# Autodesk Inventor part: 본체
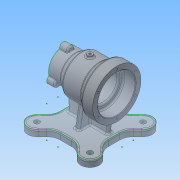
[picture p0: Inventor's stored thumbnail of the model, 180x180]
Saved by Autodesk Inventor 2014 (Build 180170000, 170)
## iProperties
Created: 2017-03
Part Number: 본체
Material: 일반
Document SubType Name: Modeling
Designer: NET
Density: 1 g/cm^3
Appearance: 기본값
Author: NET
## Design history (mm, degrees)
sketch "스케치1"
  geometry: L1 (-45, 45)-(45, 45); L2 (45, 45)-(45, -45); L3 (45, -45)-(-45, -45); L4 (-45, -45)-(-45, 45); L5 (-12.021, 12.021)-(-49.497, 49.497); L6 (0, 0)-(-49.497, -49.497); L7 (0, 0)-(-38.765, 0); L8 (-24.042, 0)-(-61.518, -37.477); L9 (0, -24.042)-(-37.477, -61.518); L10 (-24.042, 0)-(-73.539, 49.497); L11 (0, 24.042)-(-49.497, 73.539); L12 (12.021, -12.021)-(49.497, -49.497); L13 (0, 0)-(49.497, 49.497); L14 (24.042, 0)-(73.539, -49.497); L15 (0, -24.042)-(49.497, -73.539); L16 (0, 24.042)-(37.477, 61.518); L17 (24.042, 0)-(61.518, 37.477); C1 r 17 at (-49.497, 49.497); C2 r 17 at (-49.497, -49.497); C3 r 17 at (49.497, 49.497); C4 r 17 at (49.497, -49.497); A1 r 70 centre (0, 0) between (-60.036, -35.995) and (-35.995, -60.036); A2 r 70 centre (0, 0) between (35.995, -60.036) and (60.036, -35.995); A3 r 70 centre (0, 0) between (60.036, 35.995) and (35.995, 60.036); A4 r 70 centre (0, 0) between (-35.995, 60.036) and (-60.036, 35.995); A5 r 25 centre (-70, 10.603) between (-45, 10.603) and (-52.322, 28.281); A6 r 25 centre (-70, -10.603) between (-52.322, -28.281) and (-45, -10.603); A7 r 25 centre (-10.603, -70) between (-10.603, -45) and (-28.281, -52.322); A8 r 25 centre (10.603, -70) between (28.281, -52.322) and (10.603, -45); A9 r 25 centre (70, 10.603) between (52.322, 28.281) and (45, 10.603); A10 r 25 centre (70, -10.603) between (45, -10.603) and (52.322, -28.281); A11 r 25 centre (-10.603, 70) between (-28.281, 52.322) and (-10.603, 45); A12 r 25 centre (10.603, 70) between (10.603, 45) and (28.281, 52.322); 3 further points
  constraints: 34 end point, 29 point on circle, 25 point on line, 16 centre point, 16 tangent, 10 parallel, 4 coincident, 2 midpoint, 2 perpendicular, 1 horizontal, 1 horizontal alignment, 1 vertical alignment
  dimensions: "d0" = 90 distance of L1.start L1.end; "d1" = 90 distance of L1.end L2.end; "d3" = 45 deg angle of L7 L5; "d4" = 45 deg angle of L6 L7; "d5" = 34 diameter of C1; "d6" = 34 diameter of C2; "d7" = 17 distance between parallel lines of L11 L5; "d8" = 17 distance between parallel lines of L5 L10; "d9" = 17 distance between parallel lines of L8 L6; "d10" = 17 distance between parallel lines of L9 L6; "d11" = 49.49747 horizontal distance of point (0, 0) C2.centre; "d12" = 45 deg angle of L7 L13; "d13" = 45 deg angle of L7 L12; "d14" = 34 diameter of C3; "d15" = 34 diameter of C4; "d16" = 17 distance between parallel lines of L16 L13; "d17" = 17 distance between parallel lines of L17 L13; "d18" = 17 distance between parallel lines of L14 L12; "d19" = 17 distance between parallel lines of L15 L12; "d20" = 49.49747 horizontal distance of point (0, 0) L5.end; "d21" = 70 distance from line of L12 L13.end; "d22" = 49.49747 horizontal distance of point (0, 0) L6.end; "d23" = 49.49747 horizontal distance of point (0, 0) C4.centre; "d26" = 50 diameter of A5; "d27" = 50 diameter of A6; "d28" = 50 diameter of A7; "d29" = 50 diameter of A8; "d30" = 50 diameter of A9; "d31" = 50 diameter of A10; "d32" = 50 diameter of A11; "d33" = 50 diameter of A12; "d34" = 25 radius of A5 (derived); "d35" = 70 distance of L9.start L15.end; "d36" = 70 distance of L14.start L14.end; "d37" = 70 distance of L12.start L17.end; "d38" = 70 distance of L5.start L16.end; "d39" = 70 distance of L11.start L11.end; "d40" = 70 distance of L8.start L10.end; "d41" = 70 distance of L5.start L8.end; "d42" = 70 distance of L12.start L9.end; "d43" = 70 distance of L6.start L13.end (derived); "d44" = 70 radius of A4 (derived); "d45" = 70 radius of A1 (derived); "d46" = 90 distance of L3.end L1.start (derived); "d47" = 12.02082 horizontal distance of L12.start point (0, 0); "d48" = 12.02082 horizontal distance of L12.start point (0, 0); "d49" = 12.02082 horizontal distance of L5.start point (0, 0); "d50" = 12.02082 horizontal distance of point (0, 0) L5.start (derived); "d51" = 24.04163 distance of point (0, 0) L8.start (derived); "d52" = 38.76502 distance of L6.start L7.end
extrude "돌출1" new body sketch "스케치1" distance "d53" = 12; taper "d54" = 0 deg
sketch "스케치2"
  geometry: L1 (-50, 82)-(50, 82); L2 (10.603, 0)-(-10.603, 0) reference; L3 (-50, 82)-(-50, 127); L4 (-50, 127)-(-30, 127); L5 (-30, 127)-(-19, 118); L6 (-19, 118)-(15, 118); L7 (15, 118)-(27, 109.5); L8 (27, 109.5)-(50, 109.5); L9 (50, 109.5)-(50, 82); L10 (-50, 117)-(-27, 117); L11 (-27, 117)-(-27, 108); L12 (-27, 108)-(20, 108); L13 (20, 108)-(20, 99.5); L14 (20, 99.5)-(50, 99.5); 3 further points
  constraints: 26 end point, 5 parallel, 5 perpendicular, 2 midpoint, 2 point on line, 1 horizontal, 1 vertical alignment
  dimensions: "d55" = 100 distance of L1.start L1.end; "d56" = 82 vertical distance of point (0, 0) L1.start; "d57" = 90 diameter of L4 L1; "d58" = 72 diameter of L6 L1; "d59" = 55 diameter of L8 L1; "d60" = 20 distance of L3.end L4.end; "d61" = 31 horizontal distance of L5.end L3.end; "d62" = 65 horizontal distance of L6.end L3.end; "d63" = 23 distance of L7.end L8.end; "d64" = 23 distance of L10.start L10.end; "d65" = 47 distance of L11.end L12.end; "d67" = 70 diameter of L10 L1; "d68" = 52 diameter of L12 L1; "d69" = 35 diameter of L14 L1
revolve "회전1" stored, may be unused: angle "d70" = 90 deg
sketch "스케치3"
  geometry: L1 (10.603, 0)-(-10.603, 0) reference; L2 (10.603, 12)-(-10.603, 12) reference; L3 (0, 12)-(-37, 12); L4 (-37, 12)-(-37, 72); L5 (-37, 72)-(37, 72); L6 (37, 72)-(37, 12); L7 (37, 12)-(0, 12); 1 further point
  constraints: 10 end point, 2 perpendicular, 2 point on line, 1 collinear, 1 midpoint, 1 parallel
  dimensions: "d71" = 37 distance of L3.end L3.start; "d72" = 37 distance of L6.end L3.start; "d73" = 60 distance of L3.end L4.end
extrude "돌출2" join sketch "스케치3" stored distance "d74" = 8; taper "d75" = 0 deg
sketch "스케치4"
  geometry: L1 (10.603, 0)-(-10.603, 0) reference; L2 (4, 12)-(4, 54.792) reference; L3 (-4, 12)-(4, 12) reference; L4 (-4, 54.792)-(-4, 12) reference; L5 (0, 12)-(-25, 12); L6 (-25, 12)-(-15.302, 67); L7 (-15.302, 67)-(0, 67); L8 (0, 67)-(0, 12); L9 (0, 12)-(25, 12); L10 (25, 12)-(15.302, 67); L11 (15.302, 67)-(0, 67); L12 (-36.106, 12)-(-66.497, 12) reference; L13 (35.995, 12)-(28.281, 12) reference; A1 r 27.5 centre (0, 82) between (-4, 54.792) and (4, 54.792) reference; 2 further points
  constraints: 14 end point, 3 perpendicular, 2 parallel, 1 midpoint
  dimensions: "d76" = 25 distance of L5.start L5.end; "d77" = 25 distance of L5.start L9.end; "d78" = 100 deg angle of L6 L12; "d79" = 100 deg angle of L13 L10; "d80" = 55 distance of L7.end L5.start; "d81" = 15.30202 distance of L6.end L7.end (derived)
extrude "돌출3" join sketch "스케치4" stored distance "d82" = 8; taper "d83" = 0 deg
revolve "회전2" stored, may be unused: angle "d84" = 90 deg
sketch "스케치5"
  geometry: L1 (-107.4, 0)-(70.4, 0) reference; C1 r 7 at (27.5, 0); 2 further points
  constraints: 1 centre point, 1 horizontal alignment, 1 point on line, 1 other
  dimensions: "d85" = 14 diameter of C1
extrude "돌출4" join sketch "스케치5" distance "d86" = 15; taper "d87" = 0 deg
sketch "스케치6"
  geometry: C1 r 35 at (0, 0) reference; 2 further points
  constraints: 1 horizontal alignment
  dimensions: "d91" = 40 distance of C1.centre point (-40, 0)
hole "구멍1" sketch "스케치6" at (-40, 0) diameter "d92" = 3.242; stored, may be unused: countersink angle "d96" = 90 deg, drill point angle "d98" = 118 deg; dims "d93" = 9, "d94" = 4, "d95" = 2, "d97" = 11
sketch "스케치7"
  geometry: C1 r 17.5 at (-27.5, 0) reference; A1 r 27.5 centre (-27.5, 0) between (-34.792, -26.516) and (-0.891, -6.943) reference; A2 r 7 centre (0, 0) between (-0.891, -6.943) and (-0.891, 6.943) reference; A3 r 27.5 centre (-27.5, 0) between (-0.891, 6.943) and (-34.792, 26.516) reference; A4 r 7 centre (-41.25, 23.816) between (-34.792, 26.516) and (-46.817, 19.573) reference; A5 r 27.5 centre (-27.5, 0) between (-46.817, 19.573) and (-46.817, -19.573) reference; A6 r 7 centre (-41.25, -23.816) between (-46.817, -19.573) and (-34.792, -26.516) reference; 1 further point
hole "구멍2" diameter "d104" = 3.242; stored, may be unused: countersink angle "d108" = 90 deg, drill point angle "d110" = 118 deg; dims "d102" = 10, "d103" = 10, "d105" = 9, "d106" = 4, "d107" = 2, "d109" = 11
node "작업 평면1"
sketch "스케치8"
  geometry: L1 (4, 4)-(4, 18.14) reference; L2 (4, 18.14)-(-4, 18.14) reference; L3 (-4, 18.14)-(-4, 4) reference; L4 (-4, 4)-(-15, 4) reference; L5 (-15, -4)-(-15, 4) reference; L6 (-15, -4)-(-4, -4) reference; L7 (-4, -4)-(-4, -18.14) reference; L8 (-4, -18.14)-(4, -18.14) reference; L9 (4, -18.14)-(4, -4) reference; L10 (4, -4)-(19, -4) reference; L11 (19, -4)-(19, 4) reference; L12 (19, 4)-(4, 4) reference; L13 (50, 45)-(50, -45) reference; C1 r 5 at (0, 0); 1 further point
  constraints: 1 centre point, 1 coincident
  dimensions: "d115" = 10 diameter of C1; "d116" = 50 distance from line of C1.centre L13 (derived)
extrude "돌출5" join sketch "스케치8" stored distance "d117" = 15; taper "d118" = 0 deg
hole "구멍3" diameter "d121" = 4.134; stored, may be unused: countersink angle "d125" = 90 deg, drill point angle "d127" = 118 deg; dims "d119" = 10, "d120" = 10, "d122" = 9, "d123" = 4, "d124" = 2, "d126" = 32.25
chamfer "모따기1" distance "d128" = 1; stored, may be unused: second distance "d129" = 2, angle "d130" = 45 deg
chamfer "모따기2" distance "d131" = 1; stored, may be unused: second distance "d132" = 2, angle "d133" = 45 deg
fillet "모깎기1" dims "d134" = 3
fillet "모깎기2" dims "d135" = 3
fillet "모깎기3" dims "d136" = 3
fillet "모깎기4" dims "d137" = 1
fillet "모깎기5" dims "d138" = 3
fillet "모깎기6" dims "d139" = 1
fillet "모깎기7" dims "d140" = 3
fillet "모깎기8" dims "d141" = 1
sketch "스케치9"
  geometry: L1 (4, 25)-(4, 4) reference; L2 (4, 4)-(37, 4) reference; L3 (37, 4)-(37, -4) reference; L4 (37, -4)-(4, -4) reference; L5 (4, -4)-(4, -25) reference; L6 (4, -25)-(-4, -25) reference; L7 (-4, -25)-(-4, -4) reference; L8 (-4, -4)-(-37, -4) reference; L9 (-37, -4)-(-37, 4) reference; L10 (-37, 4)-(-4, 4) reference; L11 (-4, 4)-(-4, 25) reference; L12 (-4, 25)-(4, 25) reference; L13 (35.995, 60.036)-(28.281, 52.322) reference; L14 (10.603, 45)-(-10.603, 45) reference; L15 (-28.281, 52.322)-(-35.995, 60.036) reference; L16 (-60.036, 35.995)-(-52.322, 28.281) reference; L17 (-45, 10.603)-(-45, -10.603) reference; L18 (-52.322, -28.281)-(-60.036, -35.995) reference; L19 (-35.995, -60.036)-(-28.281, -52.322) reference; L20 (-10.603, -45)-(10.603, -45) reference; L21 (28.281, -52.322)-(35.995, -60.036) reference; L22 (60.036, -35.995)-(52.322, -28.281) reference; L23 (45, -10.603)-(45, 10.603) reference; L24 (52.322, 28.281)-(60.036, 35.995) reference; A1 r 70 centre (0, 0) between (36.106, 59.97) and (35.995, 60.036) reference; A2 r 25 centre (10.603, 70) between (10.603, 45) and (28.281, 52.322) reference; A3 r 25 centre (-10.603, 70) between (-28.281, 52.322) and (-10.603, 45) reference; A4 r 70 centre (0, 0) between (-35.995, 60.036) and (-36.106, 59.97) reference; A5 r 17 centre (-49.497, 49.497) between (-36.106, 59.97) and (-59.97, 36.106) reference; A6 r 70 centre (0, 0) between (-59.97, 36.106) and (-60.036, 35.995) reference; A7 r 25 centre (-70, 10.603) between (-45, 10.603) and (-52.322, 28.281) reference; A8 r 25 centre (-70, -10.603) between (-52.322, -28.281) and (-45, -10.603) reference; A9 r 70 centre (0, 0) between (-60.036, -35.995) and (-59.97, -36.106) reference; A10 r 17 centre (-49.497, -49.497) between (-59.97, -36.106) and (-36.106, -59.97) reference; A11 r 70 centre (0, 0) between (-36.106, -59.97) and (-35.995, -60.036) reference; A12 r 25 centre (-10.603, -70) between (-10.603, -45) and (-28.281, -52.322) reference; A13 r 25 centre (10.603, -70) between (28.281, -52.322) and (10.603, -45) reference; A14 r 70 centre (0, 0) between (35.995, -60.036) and (36.106, -59.97) reference; A15 r 17 centre (49.497, -49.497) between (36.106, -59.97) and (59.97, -36.106) reference; A16 r 70 centre (0, 0) between (59.97, -36.106) and (60.036, -35.995) reference; A17 r 25 centre (70, -10.603) between (45, -10.603) and (52.322, -28.281) reference; A18 r 25 centre (70, 10.603) between (52.322, 28.281) and (45, 10.603) reference; A19 r 70 centre (0, 0) between (60.036, 35.995) and (59.97, 36.106) reference; A20 r 17 centre (49.497, 49.497) between (59.97, 36.106) and (36.106, 59.97) reference
hole "구멍4" diameter "d144" = 10; stored, may be unused: countersink angle "d148" = 90 deg, drill point angle "d150" = 0 deg; dims "d142" = 10, "d143" = 10, "d145" = 9, "d146" = 4, "d147" = 2, "d149" = 32.25
hole "구멍5" diameter "d153" = 10; stored, may be unused: countersink angle "d157" = 90 deg, drill point angle "d159" = 0 deg; dims "d151" = 10, "d152" = 10, "d154" = 9, "d155" = 4, "d156" = 2, "d158" = 32.25
hole "구멍6" diameter "d162" = 10; stored, may be unused: countersink angle "d166" = 90 deg, drill point angle "d168" = 0 deg; dims "d160" = 10, "d161" = 10, "d163" = 9, "d164" = 4, "d165" = 2, "d167" = 32.25
hole "구멍7" diameter "d171" = 10; stored, may be unused: countersink angle "d175" = 90 deg, drill point angle "d177" = 0 deg; dims "d169" = 10, "d170" = 10, "d172" = 9, "d173" = 4, "d174" = 2, "d176" = 32.25
fillet "모깎기9" dims "d178" = 3
fillet "모깎기10" dims "d179" = 3
fillet "모깎기11" dims "d180" = 3
fillet "모깎기12" dims "d181" = 3
fillet "모깎기13" dims "d182" = 3
fillet "모깎기14" dims "d183" = 3
sketch "스케치11"
  geometry: L1 (-45, 10.603)-(-45, -10.603) reference; A1 r 70 centre (0, 0) between (58.397, 38.598) and (58.357, 38.658) reference; 1 further point
  constraints: 1 other
  dimensions: "d184" = 35 distance of point (0, 35) A1.centre; "d185" = 45 distance from line of L1 point (0, 35)
feature "엠보싱1" sketch "스케치11" dims "d0" = 90, "d1" = 90, "d3" = 45 deg, "d4" = 45 deg, "d5" = 34, "d6" = 34, "d7" = 17, "d8" = 17, "d9" = 17, "d10" = 17, "d11" = 49.49747, "d12" = 45 deg, "d13" = 45 deg, "d14" = 34, "d15" = 34, "d16" = 17, "d17" = 17, "d18" = 17, "d19" = 17, "d20" = 49.49747, "d21" = 70, "d22" = 49.49747, "d23" = 49.49747, "d26" = 50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
node "솔리드1"
pattern_circular "원형 패턴1" dims angle "d89" = 360 deg
pattern_circular "원형 패턴2" dims angle "d100" = 360 deg
pattern_circular "원형 패턴3" dims angle "d112" = 360 deg
node "투영된 루프1"
node "투영된 루프2"
other parameters: "d114" = -122
